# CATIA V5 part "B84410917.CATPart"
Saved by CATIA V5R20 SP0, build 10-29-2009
Part number: B84410917
Revision: 3
Definition: design
Nomenclature: B84410917
Source: made
Description: NOT SPECIFIED
Bounding box of the stored display mesh (mm): x -10 to 10, y -10 to 10, z -9 to 17
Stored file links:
  C:\Users\Utente\Desktop\3D files B844\B84410917.CATPart
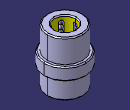
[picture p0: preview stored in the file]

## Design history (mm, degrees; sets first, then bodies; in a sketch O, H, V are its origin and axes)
Body1 "MANIFOLD_SOLID_BREP #38" (main body)
  Solid1: solid without history
Body2 "MANIFOLD_SOLID_BREP #76"
  Solid2: solid without history
Body3 "MANIFOLD_SOLID_BREP #114"
  Solid3: solid without history
Body4 "MANIFOLD_SOLID_BREP #152"
  Solid4: solid without history
Body5 "MANIFOLD_SOLID_BREP #190"
  Solid5: solid without history
Body6 "MANIFOLD_SOLID_BREP #228"
  Solid6: solid without history
Body7 "MANIFOLD_SOLID_BREP #266"
  Solid7: solid without history
Body8 "MANIFOLD_SOLID_BREP #304"
  Solid8: solid without history
Body9 "MANIFOLD_SOLID_BREP #1958"
  Solid9: solid without history
Body10 "MANIFOLD_SOLID_BREP #1996"
  Solid10: solid without history
Body11 "MANIFOLD_SOLID_BREP #2034"
  Solid11: solid without history
Body12 "MANIFOLD_SOLID_BREP #2072"
  Solid12: solid without history
Body13 "MANIFOLD_SOLID_BREP #2110"
  Solid13: solid without history
Body14 "MANIFOLD_SOLID_BREP #2148"
  Solid14: solid without history
Body15 "MANIFOLD_SOLID_BREP #2186"
  Solid15: solid without history
Body16 "MANIFOLD_SOLID_BREP #2224"
  Solid16: solid without history
Body17 "MANIFOLD_SOLID_BREP #2262"
  Solid17: solid without history
Body18 "MANIFOLD_SOLID_BREP #2300"
  Solid18: solid without history
Body19 "MANIFOLD_SOLID_BREP #2338"
  Solid19: solid without history
Body20 "MANIFOLD_SOLID_BREP #2376"
  Solid20: solid without history
Body21 "MANIFOLD_SOLID_BREP #2414"
  Solid21: solid without history
Body22 "MANIFOLD_SOLID_BREP #2452"
  Solid22: solid without history
Body23 "MANIFOLD_SOLID_BREP #2490"
  Solid23: solid without history
Body24 "MANIFOLD_SOLID_BREP #2528"
  Solid24: solid without history
Body25 "MANIFOLD_SOLID_BREP #2566"
  Solid25: solid without history
Body26 "MANIFOLD_SOLID_BREP #2604"
  Solid26: solid without history
Body27 "MANIFOLD_SOLID_BREP #2642"
  Solid27: solid without history
Body28 "MANIFOLD_SOLID_BREP #2680"
  Solid28: solid without history
Body29 "MANIFOLD_SOLID_BREP #2718"
  Solid29: solid without history
Body30 "MANIFOLD_SOLID_BREP #2756"
  Solid30: solid without history
Body31 "MANIFOLD_SOLID_BREP #2794"
  Solid31: solid without history
Body32 "MANIFOLD_SOLID_BREP #2832"
  Solid32: solid without history
Body33 "MANIFOLD_SOLID_BREP #2870"
  Solid33: solid without history
Body34 "MANIFOLD_SOLID_BREP #2908"
  Solid34: solid without history
Body35 "MANIFOLD_SOLID_BREP #2946"
  Solid35: solid without history
Body36 "MANIFOLD_SOLID_BREP #2984"
  Solid36: solid without history
Body37 "MANIFOLD_SOLID_BREP #3022"
  Solid37: solid without history
Body38 "MANIFOLD_SOLID_BREP #3060"
  Solid38: solid without history
Body39 "MANIFOLD_SOLID_BREP #3098"
  Solid39: solid without history
Body40 "MANIFOLD_SOLID_BREP #3136"
  Solid40: solid without history
Body41 "MANIFOLD_SOLID_BREP #3174"
  Solid41: solid without history
Body42 "MANIFOLD_SOLID_BREP #3212"
  Solid42: solid without history
Body43 "MANIFOLD_SOLID_BREP #3250"
  Solid43: solid without history
Body44 "MANIFOLD_SOLID_BREP #3288"
  Solid44: solid without history
Body45 "MANIFOLD_SOLID_BREP #3326"
  Solid45: solid without history
Body46 "MANIFOLD_SOLID_BREP #3364"
  Solid46: solid without history
Body47 "MANIFOLD_SOLID_BREP #3402"
  Solid47: solid without history
Body48 "MANIFOLD_SOLID_BREP #3440"
  Solid48: solid without history
Body49 "MANIFOLD_SOLID_BREP #3478"
  Solid49: solid without history
Body50 "MANIFOLD_SOLID_BREP #3516"
  Solid50: solid without history
Body51 "MANIFOLD_SOLID_BREP #3554"
  Solid51: solid without history
Body52 "MANIFOLD_SOLID_BREP #3592"
  Solid52: solid without history
Body53 "MANIFOLD_SOLID_BREP #3630"
  Solid53: solid without history
Body54 "MANIFOLD_SOLID_BREP #3668"
  Solid54: solid without history
Body55 "MANIFOLD_SOLID_BREP #3706"
  Solid55: solid without history
Body56 "MANIFOLD_SOLID_BREP #3744"
  Solid56: solid without history
Body57 "MANIFOLD_SOLID_BREP #3782"
  Solid57: solid without history
Body58 "MANIFOLD_SOLID_BREP #3820"
  Solid58: solid without history
Body59 "MANIFOLD_SOLID_BREP #3858"
  Solid59: solid without history
Body60 "MANIFOLD_SOLID_BREP #3896"
  Solid60: solid without history
Body61 "MANIFOLD_SOLID_BREP #3934"
  Solid61: solid without history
